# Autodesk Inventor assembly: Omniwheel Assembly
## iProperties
Created: 2007-11
Part Number: Omniwheel Assembly
Document SubType Name: Assembly
Designer: lwoods
Mass: 807.037 g
Surface Area: 1296.28 cm^2
Volume: 334.333 cm^3
Density: 2.41387 g/cm^3
Author: lwoods
